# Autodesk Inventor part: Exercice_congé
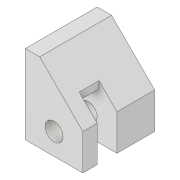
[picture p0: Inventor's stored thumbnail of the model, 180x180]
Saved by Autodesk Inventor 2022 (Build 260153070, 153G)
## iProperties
Created: 2018-06
Part Number: Exercice_congé
Material: Plastique ABS
Document SubType Name: Modeling
Designer: Fabian Perrée
Density: 1.06 g/cm^3
Appearance: Lisse - Blanc
Author: Fabian Perrée
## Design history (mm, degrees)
sketch "Esquisse1"
  geometry: L1 (0, 0)-(0, 13); L2 (0, 22)-(4, 22); L3 (4, 22)-(11, 15); L4 (16, 10)-(16, 0); L5 (16, 0)-(0, 0); L6 (0, 13)-(11, 13); L7 (11, 13)-(11, 15); L8 (11, 15)-(16, 10); L9 (0, 13)-(0, 22); C1 r 2.5 at (8, 6)
  constraints: 18 end point, 4 perpendicular, 2 parallel, 2 vertical, 1 centre point, 1 collinear, 1 horizontal
  dimensions: "d1" = 4 distance of L2.start L2.end; "d2" = 135 deg angle of L2 L3; "d3" = 5 diameter of C1; "d4" = 6 distance from line of L5 C1.centre; "d5" = 8 distance from line of L1 C1.centre; "d9" = 3 distance from line of C1.centre L7; "d18" = 13 distance between parallel lines of L5 L6; "d20" = 16 distance from line of L2 C1.centre; "d21" = 16 distance between parallel lines of L4 L1
extrude "Extrusion1" new body sketch "Esquisse1" distance "d10" = 4; taper "d12" = 0 deg; dims "d11" = 16, "d13" = 0
extrude "Extrusion2" join sketch "Esquisse1" distance "d14" = 4; taper "d15" = 0 deg
node "Plan de construction1"
node "Plan de construction2"
extrude "Extrusion3" join sketch "Esquisse1" stored distance "d16" = 10; taper "d17" = 0 deg
node "Solide1"
other parameters: "d19" = 5.5
